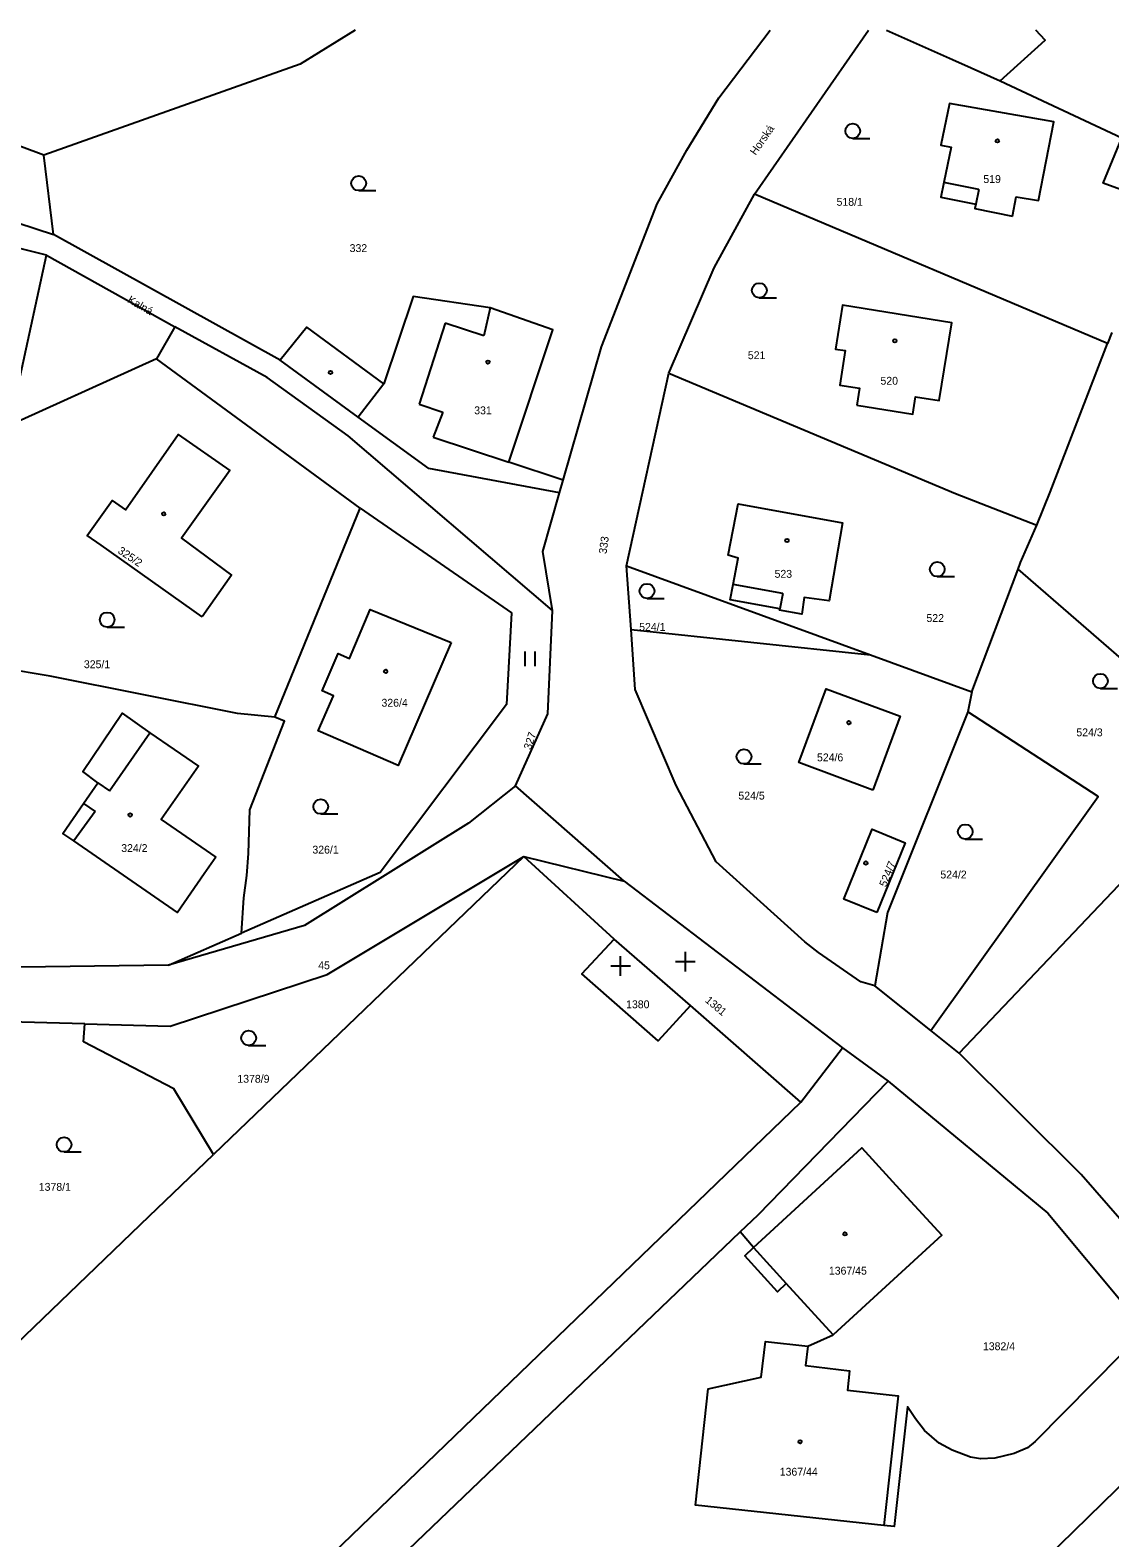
# Model space of a CAD drawing. Extents: x -719706 to -718922, y -950351 to -949651.
# Drawn here: x -719594.9 to -719485, y -949804.5 to -949651 of the extents above; entities that cross this region are included whole.
import ezdxf

# ---------------------------------------------------------------- set-up
doc = ezdxf.new("R2010")
doc.units = 0
doc.layers.add('Doplňující texty', color=7, linetype='Continuous')

msp = doc.modelspace()

# ---------------------------------------------------------------- linework, layer by layer
at = {"layer": 'Doplňující texty'}
for p, q in [((-719521.17, -949667.73), (-719509.56, -949651.04)), ((-719496.16, -949656.18), (-719483.78, -949661.99)), ((-719511.16, -949662.05), (-719509.41, -949662.05)), ((-719592.52, -949671.82), (-719593.5, -949663.75)), ((-719498.34, -949667.25), (-719501.88, -949666.54)), ((-719593.21, -949673.95), (-719620.8, -949666.93)), ((-719561.45, -949667.37), (-719559.7, -949667.37)), ((-719485.22, -949682.94), (-719521.17, -949667.73)), ((-719498.34, -949667.25), (-719498.64, -949668.76)), ((-719569.44, -949684.61), (-719592.52, -949671.82)), ((-719593.21, -949673.95), (-719580.15, -949681.24)), ((-719520.67, -949678.27), (-719518.92, -949678.27)), ((-719548.05, -949679.3), (-719548.72, -949682.13)), ((-719580.15, -949681.24), (-719582.02, -949684.5)), ((-719552.65, -949680.85), (-719555.3, -949689.1)), ((-719548.72, -949682.13), (-719552.65, -949680.85)), ((-719484.78, -949681.79), (-719485.22, -949682.94)), ((-719582.02, -949684.5), (-719606.19, -949695.42)), ((-719561.3, -949699.7), (-719582.02, -949684.5)), ((-719534.18, -949705.57), (-719529.89, -949685.94)), ((-719558.88, -949687.03), (-719561.5, -949690.42)), ((-719555.3, -949689.1), (-719552.9, -949689.9)), ((-719552.9, -949689.9), (-719553.87, -949692.47)), ((-719553.87, -949692.47), (-719546.15, -949695.02)), ((-719541, -949698.14), (-719540.63, -949696.84)), ((-719570, -949720.95), (-719561.3, -949699.7)), ((-719533.73, -949712.05), (-719534.18, -949705.57)), ((-719534.18, -949705.57), (-719509.37, -949714.62)), ((-719502.56, -949706.65), (-719500.81, -949706.65)), ((-719499.03, -949718.39), (-719494.34, -949705.89)), ((-719471.96, -949725.3), (-719494.34, -949705.89)), ((-719518.29, -949708.36), (-719523.34, -949707.44)), ((-719532.1, -949708.87), (-719530.35, -949708.87)), ((-719518.29, -949708.36), (-719518.58, -949709.93)), ((-719587.05, -949711.79), (-719585.3, -949711.79)), ((-719533.73, -949712.05), (-719509.37, -949714.62)), ((-719544.49, -949715.76), (-719544.49, -949714.26)), ((-719543.49, -949715.76), (-719543.49, -949714.26)), ((-719509.37, -949714.62), (-719499.03, -949718.39)), ((-719499.03, -949718.39), (-719499.46, -949720.43)), ((-719485.95, -949718.03), (-719484.2, -949718.03)), ((-719586.81, -949728.47), (-719582.72, -949722.54)), ((-719522.23, -949725.72), (-719520.48, -949725.72)), ((-719500.34, -949755.14), (-719471.96, -949725.3)), ((-719588, -949727.65), (-719586.81, -949728.47)), ((-719534.44, -949737.65), (-719545.49, -949727.93)), ((-719588.26, -949730.57), (-719590.45, -949733.55)), ((-719589.45, -949729.74), (-719588.26, -949730.57)), ((-719565.31, -949730.81), (-719563.56, -949730.81)), ((-719499.71, -949733.37), (-719497.96, -949733.37)), ((-719544.65, -949735.14), (-719576.22, -949765.46)), ((-719535.43, -949743.55), (-719544.65, -949735.14)), ((-719544.65, -949735.14), (-719534.44, -949737.65)), ((-719534.44, -949737.65), (-719512.2, -949754.61)), ((-719580.8, -949746.19), (-719573.38, -949742.94)), ((-719527.69, -949750.31), (-719535.43, -949743.55)), ((-719528.19, -949746.85), (-719528.19, -949744.85)), ((-719580.8, -949746.19), (-719608.49, -949746.58)), ((-719533.79, -949746.29), (-719535.79, -949746.29)), ((-719534.79, -949747.29), (-719534.79, -949745.29)), ((-719527.19, -949745.85), (-719529.19, -949745.85)), ((-719503.21, -949752.85), (-719508.91, -949748.3)), ((-719516.44, -949760.14), (-719527.69, -949750.31)), ((-719589.32, -949752.18), (-719605.6, -949751.73)), ((-719589.46, -949754), (-719589.32, -949752.18)), ((-719580.25, -949758.78), (-719589.46, -949754)), ((-719500.34, -949755.14), (-719503.21, -949752.85)), ((-719572.65, -949754.36), (-719570.9, -949754.36)), ((-719572.65, -949754.36), (-719570.9, -949754.36)), ((-719516.44, -949760.14), (-719512.2, -949754.61)), ((-719512.2, -949754.61), (-719507.56, -949758.01)), ((-719576.22, -949765.46), (-719580.25, -949758.78)), ((-719591.44, -949765.21), (-719589.69, -949765.21)), ((-719582.76, -949771.75), (-719576.22, -949765.46)), ((-719597.18, -949785.61), (-719582.76, -949771.75)), ((-719561.18, -949810.26), (-719522.61, -949773.32)), ((-719521.26, -949774.94), (-719522.61, -949773.32)), ((-719521.26, -949774.94), (-719517.93, -949778.59)), ((-719515.74, -949784.96), (-719513.14, -949783.82)), ((-719481.29, -949796.6), (-719529.7, -949843.78))]:
    msp.add_line(p, q, dxfattribs=at)
for points in [[(-719639.91, -949651.04), (-719627.98, -949659.57), (-719621.79, -949662.27), (-719592.52, -949671.82)], [(-719593.5, -949663.75), (-719618.16, -949654.55), (-719623.21, -949651.04)], [(-719561.82, -949651.04), (-719567.42, -949654.49), (-719593.5, -949663.75)], [(-719540.63, -949696.84), (-719536.75, -949683.25), (-719531.07, -949668.71), (-719528.05, -949663.25), (-719524.78, -949657.91), (-719519.58, -949651.04)], [(-719507.72, -949651.04), (-719501.01, -949654.02), (-719499.1, -949654.87), (-719496.16, -949656.18)], [(-719496.16, -949656.18), (-719491.57, -949652.06), (-719492.53, -949651.04)], [(-719494.91, -949669.96), (-719494.52, -949668.01), (-719492.26, -949668.38), (-719490.68, -949660.38), (-719501.32, -949658.5), (-719502.2, -949662.74), (-719501.16, -949662.93), (-719501.88, -949666.54), (-719502.19, -949668.05), (-719498.64, -949668.76), (-719498.73, -949669.2), (-719494.91, -949669.96)], [(-719479.81, -949668.76), (-719485.67, -949666.6), (-719483.78, -949661.99)], [(-719529.89, -949685.94), (-719525.27, -949675.21), (-719521.17, -949667.73)], [(-719619.19, -949680.65), (-719595.9, -949686.29), (-719593.21, -949673.95)], [(-719540.63, -949696.84), (-719546.15, -949695.02), (-719541.69, -949681.54), (-719548.05, -949679.3), (-719555.89, -949678.15), (-719558.88, -949687.03), (-719566.73, -949681.27), (-719569.44, -949684.61)], [(-719510.74, -949689.19), (-719505.06, -949690.12), (-719504.78, -949688.36), (-719502.37, -949688.74), (-719501.06, -949680.81), (-719512.19, -949679.03), (-719512.9, -949683.49), (-719511.92, -949683.65), (-719512.47, -949687.17), (-719510.47, -949687.48), (-719510.74, -949689.19)], [(-719541.71, -949710.11), (-719562.52, -949692.32), (-719570.77, -949686.38), (-719580.15, -949681.24)], [(-719492.44, -949701.42), (-719491.06, -949698.06), (-719485.22, -949682.94)], [(-719541, -949698.14), (-719554.32, -949695.65), (-719561.5, -949690.42), (-719569.44, -949684.61)], [(-719529.89, -949685.94), (-719500.7, -949698.19), (-719492.44, -949701.42)], [(-719577.37, -949710.73), (-719587.65, -949703.44), (-719589.07, -949702.45), (-719586.54, -949698.9), (-719585.17, -949699.86), (-719579.84, -949692.19), (-719574.58, -949695.86), (-719579.48, -949702.75), (-719574.4, -949706.51), (-719577.37, -949710.73)], [(-719541.71, -949710.11), (-719542.71, -949704.09), (-719541, -949698.14)], [(-719561.3, -949699.7), (-719545.9, -949710.35), (-719546.4, -949719.65), (-719559.25, -949736.75), (-719573.38, -949742.94)], [(-719518.61, -949710.08), (-719518.58, -949709.93), (-719523.63, -949709.01), (-719523.34, -949707.44), (-719522.84, -949704.77), (-719523.84, -949704.48), (-719522.84, -949699.25), (-719512.21, -949701.18), (-719513.56, -949709.12), (-719516.1, -949708.77), (-719516.35, -949710.49), (-719518.61, -949710.08)], [(-719494.34, -949705.89), (-719494.08, -949705.2), (-719492.44, -949701.42)], [(-719552.04, -949713.34), (-719557.43, -949725.88), (-719565.56, -949722.36), (-719564.02, -949718.77), (-719565.16, -949718.28), (-719563.53, -949714.49), (-719562.4, -949714.97), (-719560.27, -949710.01), (-719552.04, -949713.34)], [(-719545.49, -949727.93), (-719542.21, -949720.6), (-719541.71, -949710.11)], [(-719508.91, -949748.3), (-719510.35, -949747.89), (-719514.65, -949744.91), (-719516.03, -949743.82), (-719525.06, -949735.67), (-719529.13, -949727.92), (-719533.3, -949718.15), (-719533.73, -949712.05)], [(-719570, -949720.95), (-719573.78, -949720.58), (-719592.85, -949716.78), (-719597.72, -949715.98)], [(-719509.13, -949728.37), (-719516.66, -949725.57), (-719513.86, -949718.06), (-719506.34, -949720.85), (-719509.13, -949728.37)], [(-719499.46, -949720.43), (-719507.64, -949740.84), (-719508.91, -949748.3)], [(-719503.21, -949752.85), (-719486.17, -949729.02), (-719499.46, -949720.43)], [(-719576, -949735.2), (-719577.18, -949736.9), (-719579.89, -949740.84), (-719590.45, -949733.55), (-719591.55, -949732.79), (-719589.45, -949729.74), (-719588, -949727.65), (-719589.52, -949726.47), (-719585.52, -949720.56), (-719582.72, -949722.54), (-719577.74, -949725.94), (-719581.55, -949731.37), (-719576, -949735.2)], [(-719573.38, -949742.94), (-719573.15, -949739.34), (-719572.82, -949737.06), (-719572.68, -949734.84), (-719572.54, -949730.37), (-719569.01, -949721.37), (-719570, -949720.95)], [(-719545.49, -949727.93), (-719550.26, -949731.76), (-719566.95, -949742.17), (-719580.8, -949746.19)], [(-719508.71, -949740.83), (-719512.07, -949739.47), (-719509.18, -949732.37), (-719505.82, -949733.74), (-719508.71, -949740.83)], [(-719589.32, -949752.18), (-719580.64, -949752.42), (-719564.66, -949747.13), (-719544.65, -949735.14)], [(-719527.69, -949750.31), (-719530.97, -949753.89), (-719538.72, -949747.08), (-719535.43, -949743.55)], [(-719480.71, -949775.75), (-719487.92, -949767.49), (-719500.34, -949755.14)], [(-719522.61, -949773.32), (-719520.8, -949771.59), (-719507.56, -949758.01)], [(-719507.56, -949758.01), (-719491.3, -949771.44), (-719475.21, -949790.69)], [(-719660.75, -949892.15), (-719657.45, -949888.39), (-719653.54, -949892.32), (-719516.44, -949760.14)], [(-719521.26, -949774.94), (-719510.22, -949764.78), (-719506.05, -949769.35), (-719502.1, -949773.66), (-719513.14, -949783.82)], [(-719513.14, -949783.82), (-719517.93, -949778.59), (-719518.83, -949779.43), (-719522.14, -949775.77), (-719521.26, -949774.94)], [(-719508, -949803.22), (-719527.17, -949801.16), (-719525.86, -949789.3), (-719520.49, -949788.13), (-719520.05, -949784.49), (-719515.74, -949784.96)], [(-719515.74, -949784.96), (-719515.96, -949786.95), (-719511.49, -949787.47), (-719511.69, -949789.44), (-719506.53, -949790.01), (-719508, -949803.22)], [(-719477.53, -949792.94), (-719483.83, -949785.83), (-719492.61, -949794.69), (-719493.36, -949795.33), (-719494.74, -949795.88), (-719496.7, -949796.36), (-719498.17, -949796.44), (-719499.18, -949796.27), (-719501.04, -949795.57), (-719502.36, -949794.85), (-719503.87, -949793.54), (-719504.79, -949792.38), (-719505.59, -949791.15), (-719506.95, -949803.33), (-719508, -949803.22)]]:
    msp.add_lwpolyline(points, dxfattribs=at)
for centre, radius in [((-719511.16, -949661.3), 0.75), ((-719496.44, -949662.31), 0.175), ((-719561.45, -949666.62), 0.75), ((-719520.67, -949677.52), 0.75), ((-719506.88, -949682.65), 0.175), ((-719548.29, -949684.82), 0.175), ((-719564.32, -949685.87), 0.175), ((-719581.29, -949700.27), 0.175), ((-719517.85, -949702.98), 0.175), ((-719502.56, -949705.9), 0.75), ((-719532.1, -949708.12), 0.75), ((-719587.05, -949711.04), 0.75), ((-719558.7, -949716.29), 0.175), ((-719485.95, -949717.28), 0.75), ((-719511.55, -949721.52), 0.175), ((-719522.23, -949724.97), 0.75), ((-719565.31, -949730.06), 0.75), ((-719584.71, -949730.91), 0.175), ((-719499.71, -949732.62), 0.75), ((-719509.83, -949735.8), 0.175), ((-719572.65, -949753.61), 0.75), ((-719572.65, -949753.61), 0.75), ((-719591.44, -949764.46), 0.75), ((-719511.95, -949773.55), 0.175), ((-719516.52, -949794.7), 0.175)]:
    msp.add_circle(centre, radius, dxfattribs=at)

# ---------------------------------------------------------------- texts
for s, rotation, p in [('Horská', 55, (-719521.04, -949663.83)), ('Kalná', 330, (-719585.05, -949678.7)), ('325/2', 326, (-719586.04, -949704.2)), ('333', 82, (-719536.23, -949704.38)), ('327', 72, (-719543.92, -949724.33)), ('524/7', 68, (-719507.76, -949738.3)), ('1381', 320, (-719526.25, -949749.88))]:
    msp.add_text(s, height=0.8, rotation=rotation, dxfattribs=at).set_placement(p)
for s, p in [('519', (-719497.87, -949666.59)), ('518/1', (-719512.81, -949668.91)), ('332', (-719562.37, -949673.62)), ('521', (-719521.84, -949684.52)), ('520', (-719508.34, -949687.12)), ('331', (-719549.69, -949690.13)), ('523', (-719519.12, -949706.77)), ('522', (-719503.66, -949711.27)), ('524/1', (-719532.9, -949712.17)), ('325/1', (-719589.42, -949715.97)), ('326/4', (-719559.13, -949719.89)), ('524/3', (-719488.4, -949722.9)), ('524/6', (-719514.8, -949725.45)), ('524/5', (-719522.8, -949729.34)), ('324/2', (-719585.62, -949734.68)), ('326/1', (-719566.16, -949734.84)), ('524/2', (-719502.24, -949737.37)), ('45', (-719565.57, -949746.61)), ('1380', (-719534.23, -949750.58)), ('1378/9', (-719573.8, -949758.16)), ('1378/1', (-719594.01, -949769.16)), ('1367/45', (-719513.59, -949777.69)), ('1382/4', (-719497.91, -949785.38)), ('1367/44', (-719518.59, -949798.15))]:
    msp.add_text(s, height=0.8, dxfattribs=at).set_placement(p)

doc.saveas('drawing.dxf')
